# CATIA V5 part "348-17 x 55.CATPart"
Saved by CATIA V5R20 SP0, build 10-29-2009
Part number: 348-17 x 55
Definition: NONE
Nomenclature: 348-17 x 55
Source: Unknown
Description: 348-17 x 55
Bounding box of the stored display mesh (mm): x 0 to 55, y -14 to 14, z -14 to 14
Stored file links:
  C:\Users\Utente\Desktop\IO LAVORO\3D X SITO CF\X SITO\3D files 348\348-17 x 55.CATPart
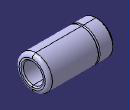
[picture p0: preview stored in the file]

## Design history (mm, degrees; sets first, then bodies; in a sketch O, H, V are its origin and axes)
Body1 "348-17 x 55" (main body)
  Solid1: solid without history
